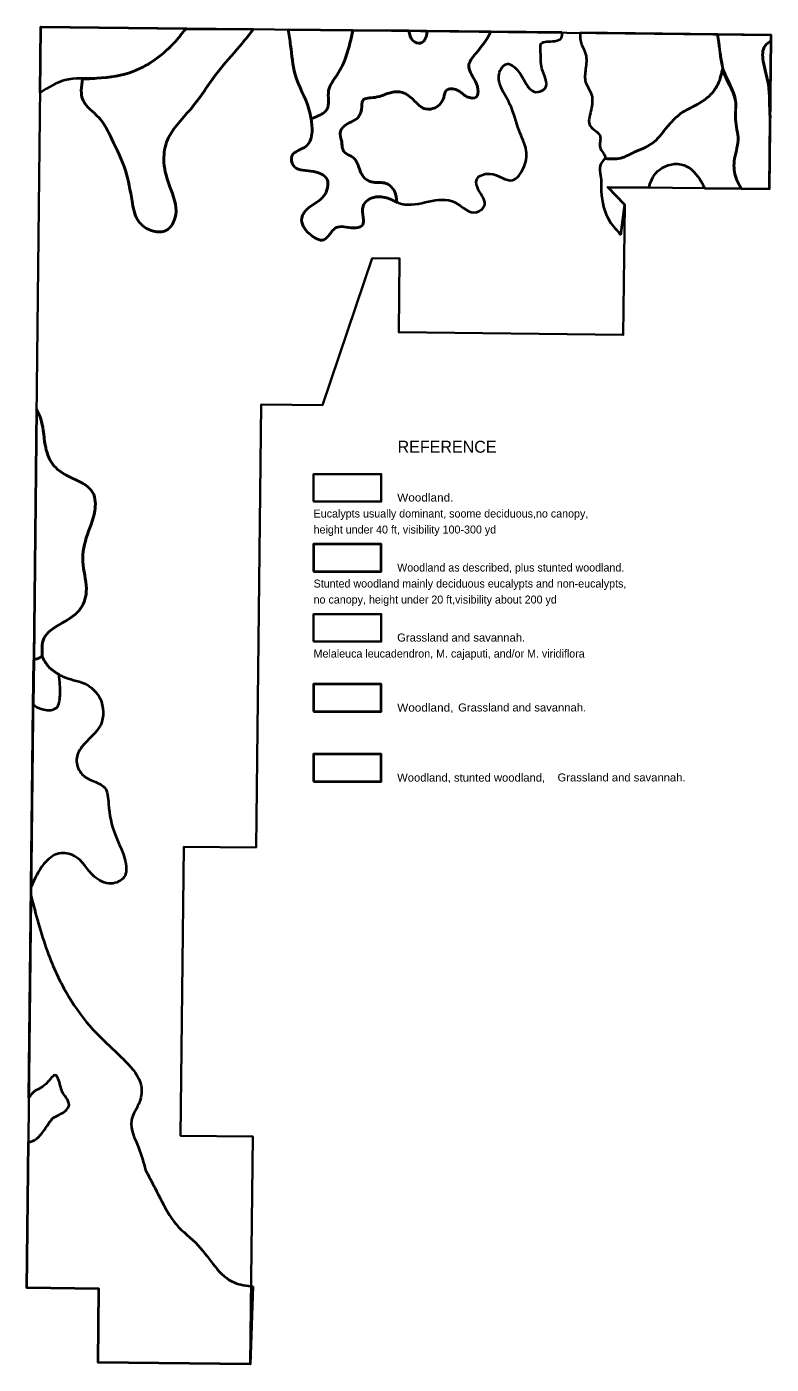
# Model space of a CAD drawing. Extents: x 796677 to 815296, y 8501154 to 8534584.
import ezdxf

# ---------------------------------------------------------------- set-up
doc = ezdxf.new("R2010")
doc.units = 0
doc.header["$LTSCALE"] = 80
for name, color, linetype, lineweight in [('19', 7, 'Continuous', 35), ('20', 7, 'Continuous', 40), ('21', 7, 'Continuous', 40), ('22', 7, 'Continuous', 40), ('23', 7, 'Continuous', 40)]:
    doc.layers.add(name, color=color, linetype=linetype, lineweight=lineweight)

msp = doc.modelspace()

# ---------------------------------------------------------------- linework, layer by layer
at = {"layer": '19'}
for points in [[(797027.79, 8534583.51), (815295.8, 8534376.89), (815251.13, 8530531.54), (811208.21, 8530578.14), (811631.27, 8530136.2), (811593.82, 8526882.94), (805979.73, 8526947.23), (806000.72, 8528792.3), (805316.55, 8528800.06), (804070.16, 8525123.41), (802537.73, 8525140.62), (802413.3, 8514069.87), (800607.09, 8514090.19), (800525.82, 8506864.46), (802331.51, 8506844.03), (802266.85, 8501153.87), (798461.72, 8501197.01), (798482.57, 8503042.05), (796677.33, 8503062.38)], [(803851.52, 8522717.16), (805540.98, 8522717.16), (805540.98, 8523404.04), (803851.52, 8523404.04)]]:
    msp.add_lwpolyline(points, close=True, dxfattribs=at)
at = {"layer": '20'}
for p, q in [((808284.63, 8534456.19), (806682.4, 8534474.31)), ((814086.36, 8533556.13), (814085.71, 8533559.77)), ((813629.94, 8530550.23), (814542.86, 8530539.7)), ((805935.23, 8530196.75), (805941.87, 8530193.94)), ((805941.87, 8530193.94), (805935.23, 8530196.75)), ((796921.47, 8525021.19), (796851.9, 8518763.39)), ((797066.43, 8518842.3), (797066.5, 8518842.11)), ((796730.14, 8507812.66), (796839.33, 8517633.24))]:
    msp.add_line(p, q, dxfattribs=at)
for points in [[(806236.42, 8534479.36), (804830.02, 8534492), (804830.57, 8534495.26)], [(811531.3, 8529383.54), (811631.27, 8530136.2), (811208.21, 8530578.14), (812241.71, 8530566.23)], [(802334.86, 8503097.23), (802266.85, 8501153.87), (798461.72, 8501197.01), (798482.57, 8503042.05), (796677.33, 8503062.38), (796717.88, 8506709.41)]]:
    msp.add_lwpolyline(points, dxfattribs=at)
at = {"layer": '20', "lineweight": 35}
msp.add_lwpolyline([(803851.52, 8519217.16), (805540.98, 8519217.16), (805540.98, 8519904.04), (803851.52, 8519904.04)], close=True, dxfattribs=at)
at = {"layer": '20'}
for points in [[(804830.57, 8534495.26), (804668.33, 8533855.81), (804439.8, 8533383.14), (804226.5, 8532986.7), (804180.8, 8532514.03), (803952.27, 8532346.31), (803790.89, 8532283.8)], [(805935.23, 8530196.75), (805871.93, 8530470.87), (805658.64, 8530669.09), (805338.69, 8530699.58), (805155.87, 8530775.82), (804988.28, 8531050.27), (804851.16, 8531309.48), (804622.63, 8531446.71), (804546.45, 8531736.41), (804515.98, 8531934.63), (804683.57, 8532148.09), (804912.1, 8532270.07), (805049.22, 8532514.03), (805079.69, 8532742.74), (805384.4, 8532818.98), (805795.76, 8532940.96), (806069.99, 8532940.96), (806374.7, 8532727.5), (806648.94, 8532529.28), (806892.71, 8532559.77), (807106, 8532818.98), (807166.95, 8532986.7), (807441.18, 8533001.95), (807684.95, 8532834.23), (807928.72, 8532834.23), (807959.19, 8533017.2), (807867.78, 8533276.4), (807730.66, 8533611.85), (807883.01, 8533886.3), (808157.25, 8534237), (808284.63, 8534456.19)], [(806682.4, 8534474.31), (806664.18, 8534328.48), (806527.06, 8534176.01), (806329, 8534237), (806236.42, 8534479.36)], [(814085.71, 8533559.77), (813965.77, 8533155.3), (813788.51, 8532897.27), (813498.45, 8532671.49), (813079.47, 8532445.71), (812660.5, 8532042.53), (812322.1, 8531671.6), (811870.89, 8531445.82), (811532.49, 8531300.68), (811142.31, 8531288.69)], [(814542.86, 8530539.7), (814416.97, 8530800.74), (814368.63, 8531220.04), (814465.31, 8531752.24), (814400.85, 8532268.31), (814400.85, 8532735.99), (814094.68, 8533510.1), (814086.36, 8533556.13)], [(805941.87, 8530193.94), (805673.99, 8530306.7), (805315, 8530306.7), (805086.54, 8530094.39), (805053.91, 8529604.46), (804858.09, 8529555.47), (804401.18, 8529555.47), (804107.46, 8529261.51), (803748.46, 8529408.49), (803552.64, 8529800.44), (803732.14, 8530061.73), (804107.46, 8530355.69), (804189.05, 8530763.96), (803781.09, 8530976.27), (803340.51, 8531123.24), (803307.87, 8531351.88), (803666.87, 8531596.84), (803813.73, 8531956.12), (803790.88, 8532283.84)], [(803790.88, 8532283.84), (803813.73, 8531956.12), (803666.87, 8531596.84), (803307.87, 8531351.88), (803340.51, 8531123.24), (803781.09, 8530976.27), (804189.05, 8530763.96), (804107.46, 8530355.69), (803732.14, 8530061.73), (803552.64, 8529800.44), (803748.46, 8529408.49), (804107.46, 8529261.51), (804401.18, 8529555.47), (804858.09, 8529555.47), (805053.91, 8529604.46), (805086.54, 8530094.39), (805315, 8530306.7), (805673.99, 8530306.7), (805941.87, 8530193.94)], [(811142.98, 8531291.8), (811013.28, 8531106.91), (811029.6, 8530861.95), (811045.92, 8530470.01), (811258.05, 8529718.78), (811531.3, 8529383.54)], [(812241.71, 8530566.23), (812253.46, 8530616.98), (812498.23, 8531008.93), (813118.32, 8531123.24), (813542.59, 8530714.97), (813629.94, 8530550.23)], [(796921.47, 8525021.19), (797009.08, 8524832.55), (797139.63, 8524130.32), (797319.13, 8523656.72), (797727.08, 8523346.43), (798330.85, 8522938.16), (798379.8, 8522480.89), (798167.67, 8521811.32), (798086.08, 8521125.42), (798167.67, 8520455.85), (797988.17, 8519995.32), (797514.94, 8519652.36), (797106.99, 8519293.08), (797066.5, 8518842.11)], [(797066.5, 8518842.11), (797106.99, 8519293.08), (797514.94, 8519652.36), (797988.17, 8519995.32), (798167.67, 8520455.85), (798086.08, 8521125.42), (798167.67, 8521811.32), (798379.8, 8522480.89), (798330.85, 8522938.16), (797727.08, 8523346.43), (797319.13, 8523656.72), (797139.63, 8524130.32), (797009.08, 8524832.55), (796921.47, 8525021.19)], [(797066.43, 8518842.3), (796889.75, 8518773.7), (796851.9, 8518763.39)], [(796851.9, 8518763.39), (796889.75, 8518773.7), (797066.43, 8518842.3)], [(797483.57, 8518400.45), (797580.22, 8518345.89), (798118.71, 8518166.25), (798510.35, 8517790.63), (798526.67, 8517137.4), (798053.44, 8516582.14), (797922.9, 8516271.85), (798037.12, 8515928.9), (798330.85, 8515732.93), (798624.58, 8515569.62), (798722.48, 8515161.35), (798885.66, 8514393.79), (799146.75, 8513707.89), (799114.12, 8513332.28), (798787.76, 8513168.97), (798363.49, 8513348.61), (797873.94, 8513854.87), (797482.31, 8513920.19), (797106.99, 8513658.9), (796788.76, 8513084.47)], [(796839.33, 8517633.24), (797107.15, 8517514.91), (797417.72, 8517561.53), (797510.89, 8517872.34), (797486.22, 8518393.78)], [(796786.23, 8512857.3), (797188.58, 8511483.61), (797727.08, 8510340.44), (798330.85, 8509523.89), (799146.75, 8508723.68), (799538.39, 8508119.43), (799505.75, 8507727.49), (799293.62, 8507237.56), (799473.12, 8506567.99), (799650.81, 8506005.84)], [(796717.88, 8506709.41), (796812.82, 8506726.09), (797016.51, 8506875.58), (797220.19, 8507160.96), (797342.4, 8507310.45), (797546.08, 8507419.16), (797736.19, 8507636.6), (797586.82, 8507921.98), (797478.19, 8508248.13), (797410.29, 8508370.44), (797165.87, 8508166.59), (796839.98, 8507949.16), (796730.14, 8507812.66)], [(799650.81, 8506005.84), (800012.44, 8505306.36), (800413.25, 8504651.89), (800961.72, 8504124.1), (801868.82, 8503195.17), (802334.86, 8503097.23)]]:
    msp.add_spline(points, degree=3, dxfattribs=at)
at = {"layer": '21'}
for p, q in [((800653.05, 8534532.97), (802350.94, 8534523.3)), ((803211.82, 8534512.42), (804830.57, 8534495.26)), ((806682.4, 8534474.31), (806236.42, 8534479.36)), ((810062.45, 8534436.08), (808284.63, 8534456.19)), ((813952.75, 8534386.73), (810513.49, 8534430.98)), ((815271.79, 8532309.86), (815294.14, 8534234.18)), ((798069.3, 8533278.16), (798069.43, 8533278.16)), ((803790.89, 8532283.8), (803790.86, 8532283.99))]:
    msp.add_line(p, q, dxfattribs=at)
msp.add_lwpolyline([(803851.52, 8520967.16), (805540.98, 8520967.16), (805540.98, 8521654.04), (803851.52, 8521654.04)], close=True, dxfattribs=at)
for points in [[(798069.3, 8533278.16), (798086.08, 8532740.01), (798477.71, 8532315.41), (798804.07, 8531776.48), (799146.75, 8530992.6), (799309.94, 8530225.04), (799456.8, 8529751.44), (799848.43, 8529473.82), (800158.48, 8529490.15), (800403.25, 8529882.09), (800256.39, 8530584.32), (800109.52, 8531188.57), (800174.79, 8531694.83), (800778.56, 8532527.71), (801447.61, 8533442.24), (802002.42, 8534095.48), (802350.94, 8534523.3)], [(802350.94, 8534523.3), (802002.42, 8534095.48), (801447.61, 8533442.24), (800778.56, 8532527.71), (800174.79, 8531694.83), (800109.52, 8531188.57), (800256.39, 8530584.32), (800403.25, 8529882.09), (800158.48, 8529490.15), (799848.43, 8529473.82), (799456.8, 8529751.44), (799309.94, 8530225.04), (799146.75, 8530992.6), (798804.07, 8531776.48), (798477.71, 8532315.41), (798086.08, 8532740.01), (798069.3, 8533278.16)], [(800660.55, 8534542.42), (800403.25, 8534226.13), (799358.89, 8533474.9), (798428.76, 8533295.26), (798069.43, 8533278.16)], [(798069.43, 8533278.16), (798428.76, 8533295.26), (799358.89, 8533474.9), (800403.25, 8534226.13), (800660.55, 8534542.42)], [(803211.63, 8534513.57), (803275.23, 8534111.81), (803389.46, 8533393.25), (803732.14, 8532527.71), (803790.86, 8532283.99)], [(803790.86, 8532283.99), (803732.14, 8532527.71), (803389.46, 8533393.25), (803275.23, 8534111.81), (803211.63, 8534513.57)], [(803790.89, 8532283.8), (803952.27, 8532346.31), (804180.8, 8532514.03), (804226.5, 8532986.7), (804439.8, 8533383.14), (804668.33, 8533855.81), (804830.57, 8534495.26)], [(804830.57, 8534495.26), (804668.33, 8533855.81), (804439.8, 8533383.14), (804226.5, 8532986.7), (804180.8, 8532514.03), (803952.27, 8532346.31), (803790.89, 8532283.8)], [(808284.63, 8534456.19), (808157.25, 8534237), (807883.01, 8533886.3), (807730.66, 8533611.85), (807867.78, 8533276.4), (807959.19, 8533017.2), (807928.72, 8532834.23), (807684.95, 8532834.23), (807441.18, 8533001.95), (807166.95, 8532986.7), (807106, 8532818.98), (806892.71, 8532559.77), (806648.94, 8532529.28), (806374.7, 8532727.5), (806069.99, 8532940.96), (805795.76, 8532940.96), (805384.4, 8532818.98), (805079.69, 8532742.74), (805049.22, 8532514.03), (804912.1, 8532270.07), (804683.57, 8532148.09), (804515.98, 8531934.63), (804546.45, 8531736.41), (804622.63, 8531446.71), (804851.16, 8531309.48), (804988.28, 8531050.27), (805155.87, 8530775.82), (805338.69, 8530699.58), (805658.64, 8530669.09), (805871.93, 8530470.87), (805935.23, 8530196.75)], [(808284.63, 8534456.19), (808157.25, 8534237), (807883.01, 8533886.3), (807730.66, 8533611.85), (807867.78, 8533276.4), (807959.19, 8533017.2), (807928.72, 8532834.23), (807684.95, 8532834.23), (807441.18, 8533001.95), (807166.95, 8532986.7), (807106, 8532818.98), (806892.71, 8532559.77), (806648.94, 8532529.28), (806374.7, 8532727.5), (806069.99, 8532940.96), (805795.76, 8532940.96), (805384.4, 8532818.98), (805079.69, 8532742.74), (805049.22, 8532514.03), (804912.1, 8532270.07), (804683.57, 8532148.09), (804515.98, 8531934.63), (804546.45, 8531736.41), (804622.63, 8531446.71), (804851.16, 8531309.48), (804988.28, 8531050.27), (805155.87, 8530775.82), (805338.69, 8530699.58), (805658.64, 8530669.09), (805871.93, 8530470.87), (805935.23, 8530196.75)], [(805934.81, 8530196.93), (806049.31, 8530159.72), (807390.66, 8530192.38), (807929.16, 8529947.41), (808124.98, 8530110.72), (807978.11, 8530502.67), (807929.16, 8530763.96), (808255.52, 8530910.94), (808826.66, 8530747.63), (809104.06, 8531057.92), (809169.34, 8531482.53), (808989.84, 8531988.79), (808761.38, 8532642.03), (808516.61, 8533131.95), (808516.61, 8533491.24), (808696.11, 8533654.55), (808924.56, 8533523.9), (809153.02, 8533180.95), (809397.79, 8532952.31), (809642.56, 8533050.3), (809560.97, 8533540.23), (809528.33, 8533948.5), (809544.65, 8534160.81), (809887.33, 8534226.13), (810050.51, 8534307.78), (810062.45, 8534436.08)], [(805934.81, 8530196.93), (806049.31, 8530159.72), (807390.66, 8530192.38), (807929.16, 8529947.41), (808124.98, 8530110.72), (807978.11, 8530502.67), (807929.16, 8530763.96), (808255.52, 8530910.94), (808826.66, 8530747.63), (809104.06, 8531057.92), (809169.34, 8531482.53), (808989.84, 8531988.79), (808761.38, 8532642.03), (808516.61, 8533131.95), (808516.61, 8533491.24), (808696.11, 8533654.55), (808924.56, 8533523.9), (809153.02, 8533180.95), (809397.79, 8532952.31), (809642.56, 8533050.3), (809560.97, 8533540.23), (809528.33, 8533948.5), (809544.65, 8534160.81), (809887.33, 8534226.13), (810050.51, 8534307.78), (810062.45, 8534436.08)], [(806236.42, 8534479.36), (806329, 8534237), (806527.06, 8534176.01), (806664.18, 8534328.48), (806682.4, 8534474.31)], [(810513.49, 8534430.98), (810540.06, 8534177.14), (810654.28, 8533899.51), (810654.28, 8533523.9), (810654.28, 8533197.28), (810784.83, 8532935.98), (810784.83, 8532478.72), (810768.51, 8532103.1), (811013.28, 8531858.14), (811013.28, 8531564.18), (811143.83, 8531302.89), (811142.8, 8531290.87)], [(814086.77, 8533553.85), (813981.88, 8534187.44), (813952.75, 8534386.73)], [(815294.14, 8534234.18), (815142.12, 8534110.03), (815093.77, 8533722.98), (815222.69, 8533142.41), (815271.03, 8532316.69), (815271.79, 8532309.86)], [(811142.31, 8531288.69), (811532.49, 8531300.68), (811870.89, 8531445.82), (812322.1, 8531671.6), (812660.5, 8532042.53), (813079.47, 8532445.71), (813498.45, 8532671.49), (813788.51, 8532897.27), (813965.77, 8533155.3), (814085.71, 8533559.77)]]:
    msp.add_spline(points, degree=3, dxfattribs=at)
at = {"layer": '22'}
for p, q in [((796851.9, 8518763.38), (796839.33, 8517633.24)), ((797489.98, 8518391.71), (797486.22, 8518393.78))]:
    msp.add_line(p, q, dxfattribs=at)
for points in [[(815294.14, 8534234.18), (815295.8, 8534376.89), (813954.58, 8534386.69)], [(814542.89, 8530539.7), (815251.13, 8530531.54), (815271.79, 8532309.86)], [(796839.33, 8517633.24), (796851.9, 8518763.38), (796839.33, 8517633.24)]]:
    msp.add_lwpolyline(points, dxfattribs=at)
msp.add_lwpolyline([(803851.52, 8515717.16), (805540.98, 8515717.16), (805540.98, 8516404.04), (803851.52, 8516404.04)], close=True, dxfattribs=at)
for points in [[(813954.58, 8534386.69), (813981.88, 8534187.44), (814094.68, 8533510.1), (814400.85, 8532735.99), (814400.85, 8532268.31), (814465.31, 8531752.24), (814368.63, 8531220.04), (814416.97, 8530800.74), (814542.89, 8530539.7)], [(815271.79, 8532309.86), (815271.03, 8532316.69), (815222.69, 8533142.41), (815093.77, 8533722.98), (815142.12, 8534110.03), (815294.14, 8534234.18)], [(797066.43, 8518842.3), (796889.75, 8518773.7), (796851.9, 8518763.38)], [(797064.2, 8518841.24), (797221.22, 8518590.85), (797489.98, 8518391.71)], [(797489.98, 8518391.71), (797221.22, 8518590.85), (797064.2, 8518841.24)], [(796839.33, 8517633.24), (797107.15, 8517514.91), (797417.72, 8517561.53), (797510.89, 8517872.34), (797486.22, 8518393.78)]]:
    msp.add_spline(points, degree=3, dxfattribs=at)
at = {"layer": '23'}
msp.add_lwpolyline([(797009.45, 8532934.39), (797027.79, 8534583.51), (800660.63, 8534542.42)], dxfattribs=at)
msp.add_lwpolyline([(803851.52, 8517467.16), (805540.98, 8517467.16), (805540.98, 8518154.04), (803851.52, 8518154.04)], close=True, dxfattribs=at)
msp.add_spline([(800660.63, 8534542.42), (800403.25, 8534226.13), (799358.89, 8533474.9), (798428.76, 8533295.26), (797629.17, 8533246.27), (797009.45, 8532934.39)], degree=3, dxfattribs=at)

# ---------------------------------------------------------------- texts
for s, height, p in [('REFERENCE', 300, (805951.23, 8523935.93)), ('Eucalypts usually dominant, soome deciduous,no canopy, ', 200, (803851.52, 8522317.16)), ('height under 40 ft, visibility 100-300 yd', 200, (803851.52, 8521917.16)), ('Woodland as described, plus stunted woodland. ', 200, (805940.98, 8520967.16)), ('Stunted woodland mainly deciduous eucalypts and non-eucalypts, ', 200, (803851.52, 8520567.16)), ('no canopy, height under 20 ft,visibility about 200 yd', 200, (803851.52, 8520167.17)), ('Melaleuca leucadendron, M. cajaputi, and/or M. viridiflora', 200, (803851.52, 8518817.16))]:
    msp.add_text(s, height=height, dxfattribs=at).set_placement(p)
for s, width, p in [('Woodland.', 1.1, (805940.98, 8522717.16)), ('Grassland and savannah.', 1.05, (805940.98, 8519217.16)), ('Woodland,', 1.1, (805940.98, 8517467.16)), ('Grassland and savannah.', 1.05, (807465.84, 8517469.45)), ('Woodland, stunted woodland, ', 1.05, (805940.98, 8515717.16)), ('Grassland and savannah.', 1.05, (809951.49, 8515720.71))]:
    msp.add_text(s, height=200, dxfattribs=dict(at, width=width)).set_placement(p)

doc.saveas('drawing.dxf')
